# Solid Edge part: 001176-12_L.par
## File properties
Last saved by: morva
Revision: 82
Accuracy: 0.990
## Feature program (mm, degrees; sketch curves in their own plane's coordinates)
body "unnamed Body 1"
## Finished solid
Body 1: solid body, 28 faces, 65 edges, 39 vertices.
  Faces by surface: cone 12, plane 8, torus 4, cylinder 2, sphere 2
  Edges by curve: circle 32, curve on surface 18, line 14, spline 1
Bounding box of the edges (mm; curved faces can reach further): 12.803 x 9.081 x 13.025, from (483.0386, 413.1684, -103.1453) to (495.8418, 422.2498, -90.12).
Cylindrical faces by radius (mm): R2.25 x2
Conical faces (half-angle, radius in mm at the cone's reference point): 45 deg R3.25 x5, 45 deg R5.7781 x7
Toroidal faces (ring radius, tube radius in mm): R3.5195 r3.0222 x4
Spherical faces by radius (mm): R11.5625 x2
Planar faces by outward normal: oblique 8
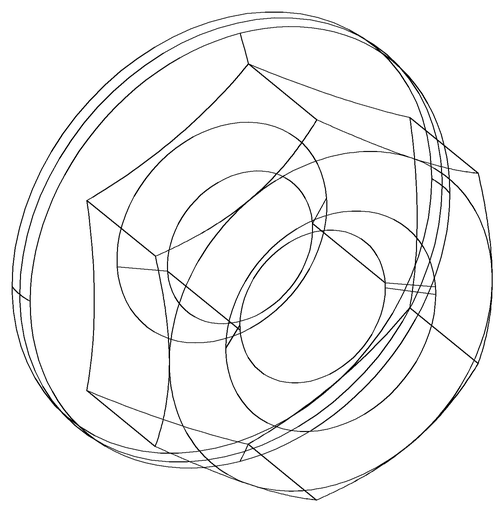
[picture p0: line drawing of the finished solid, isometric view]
